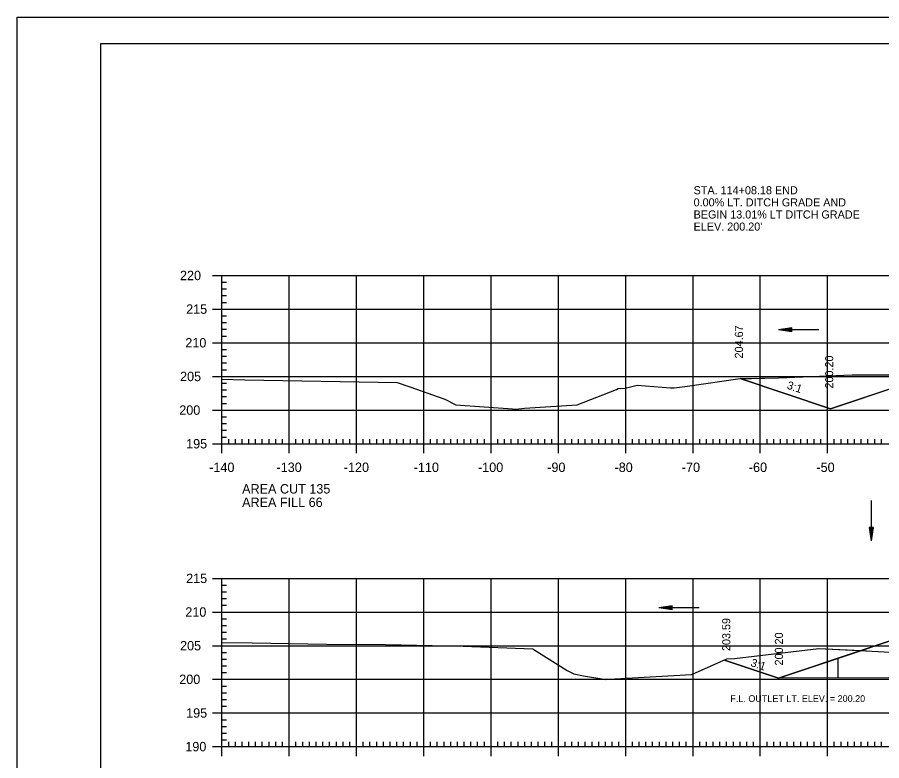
# Model space of a CAD drawing. Extents: x 1312042 to 1371461, y 379929 to 1834241.
# Drawn here: x 1371127.9 to 1371256.3, y 380031.8 to 380142.3 of the extents above; entities that cross this region are included whole.
import ezdxf

# ---------------------------------------------------------------- set-up
doc = ezdxf.new("R2010")
doc.units = 0
for name, color, linetype in [('R_Axis', 7, 'Continuous'), ('R_Axis Annot', 7, 'Continuous'), ('R_Border', 7, 'Continuous'), ('R_Drive', 7, 'Continuous'), ('R_Exist Surface', 7, 'Continuous'), ('R_Fin Surface', 7, 'Continuous'), ('R_Grid', 7, 'Continuous'), ('R_No Plot', 7, 'Continuous'), ('R_Water', 7, 'Continuous'), ('R_Water Annot', 7, 'Continuous'), ('R_Xsect Elev', 7, 'Continuous'), ('R_Xsect Slope', 7, 'Continuous')]:
    doc.layers.add(name, color=color, linetype=linetype)

msp = doc.modelspace()

# ---------------------------------------------------------------- linework, layer by layer
at = {"layer": 'R_Axis'}
for p, q in [((1371156.88, 380103.91), (1371159.68, 380103.91)), ((1371158.28, 380078.91), (1371158.28, 380103.91)), ((1371158.28, 380102.91), (1371158.98, 380102.91)), ((1371158.28, 380101.91), (1371158.98, 380101.91)), ((1371158.28, 380100.91), (1371158.98, 380100.91)), ((1371158.28, 380099.91), (1371158.98, 380099.91)), ((1371156.88, 380098.91), (1371159.68, 380098.91)), ((1371158.28, 380097.91), (1371158.98, 380097.91)), ((1371158.28, 380096.91), (1371158.98, 380096.91)), ((1371158.28, 380095.91), (1371158.98, 380095.91)), ((1371158.28, 380094.91), (1371158.98, 380094.91)), ((1371156.88, 380093.91), (1371159.68, 380093.91)), ((1371158.28, 380092.91), (1371158.98, 380092.91)), ((1371158.28, 380091.91), (1371158.98, 380091.91)), ((1371158.28, 380090.91), (1371158.98, 380090.91)), ((1371156.88, 380088.91), (1371159.68, 380088.91)), ((1371158.28, 380089.91), (1371158.98, 380089.91)), ((1371158.28, 380087.91), (1371158.98, 380087.91)), ((1371158.28, 380086.91), (1371158.98, 380086.91)), ((1371158.28, 380085.91), (1371158.98, 380085.91)), ((1371156.88, 380083.91), (1371159.68, 380083.91)), ((1371158.28, 380084.91), (1371158.98, 380084.91)), ((1371158.28, 380082.91), (1371158.98, 380082.91)), ((1371158.28, 380081.91), (1371158.98, 380081.91)), ((1371158.28, 380080.91), (1371158.98, 380080.91)), ((1371158.28, 380077.51), (1371158.28, 380080.31)), ((1371168.28, 380077.51), (1371168.28, 380080.31)), ((1371178.28, 380077.51), (1371178.28, 380080.31)), ((1371188.28, 380077.51), (1371188.28, 380080.31)), ((1371198.28, 380077.51), (1371198.28, 380080.31)), ((1371208.28, 380077.51), (1371208.28, 380080.31)), ((1371218.28, 380077.51), (1371218.28, 380080.31)), ((1371228.28, 380077.51), (1371228.28, 380080.31)), ((1371238.28, 380077.51), (1371238.28, 380080.31)), ((1371248.28, 380077.51), (1371248.28, 380080.31)), ((1371156.88, 380078.91), (1371159.68, 380078.91)), ((1371158.28, 380079.91), (1371158.98, 380079.91)), ((1371158.28, 380078.91), (1371438.28, 380078.91)), ((1371159.28, 380078.91), (1371159.28, 380079.61)), ((1371160.28, 380078.91), (1371160.28, 380079.61)), ((1371161.28, 380078.91), (1371161.28, 380079.61)), ((1371162.28, 380078.91), (1371162.28, 380079.61)), ((1371163.28, 380078.91), (1371163.28, 380079.61)), ((1371164.28, 380078.91), (1371164.28, 380079.61)), ((1371165.28, 380078.91), (1371165.28, 380079.61)), ((1371166.28, 380078.91), (1371166.28, 380079.61)), ((1371167.28, 380078.91), (1371167.28, 380079.61)), ((1371169.28, 380078.91), (1371169.28, 380079.61)), ((1371170.28, 380078.91), (1371170.28, 380079.61)), ((1371171.28, 380078.91), (1371171.28, 380079.61)), ((1371172.28, 380078.91), (1371172.28, 380079.61)), ((1371173.28, 380078.91), (1371173.28, 380079.61)), ((1371174.28, 380078.91), (1371174.28, 380079.61)), ((1371175.28, 380078.91), (1371175.28, 380079.61)), ((1371176.28, 380078.91), (1371176.28, 380079.61)), ((1371177.28, 380078.91), (1371177.28, 380079.61)), ((1371179.28, 380078.91), (1371179.28, 380079.61)), ((1371180.28, 380078.91), (1371180.28, 380079.61)), ((1371181.28, 380078.91), (1371181.28, 380079.61)), ((1371182.28, 380078.91), (1371182.28, 380079.61)), ((1371183.28, 380078.91), (1371183.28, 380079.61)), ((1371184.28, 380078.91), (1371184.28, 380079.61)), ((1371185.28, 380078.91), (1371185.28, 380079.61)), ((1371186.28, 380078.91), (1371186.28, 380079.61)), ((1371187.28, 380078.91), (1371187.28, 380079.61)), ((1371189.28, 380078.91), (1371189.28, 380079.61)), ((1371190.28, 380078.91), (1371190.28, 380079.61)), ((1371191.28, 380078.91), (1371191.28, 380079.61)), ((1371192.28, 380078.91), (1371192.28, 380079.61)), ((1371193.28, 380078.91), (1371193.28, 380079.61)), ((1371194.28, 380078.91), (1371194.28, 380079.61)), ((1371195.28, 380078.91), (1371195.28, 380079.61)), ((1371196.28, 380078.91), (1371196.28, 380079.61)), ((1371197.28, 380078.91), (1371197.28, 380079.61)), ((1371199.28, 380078.91), (1371199.28, 380079.61)), ((1371200.28, 380078.91), (1371200.28, 380079.61)), ((1371201.28, 380078.91), (1371201.28, 380079.61)), ((1371202.28, 380078.91), (1371202.28, 380079.61)), ((1371203.28, 380078.91), (1371203.28, 380079.61)), ((1371204.28, 380078.91), (1371204.28, 380079.61)), ((1371205.28, 380078.91), (1371205.28, 380079.61)), ((1371206.28, 380078.91), (1371206.28, 380079.61)), ((1371207.28, 380078.91), (1371207.28, 380079.61)), ((1371209.28, 380078.91), (1371209.28, 380079.61)), ((1371210.28, 380078.91), (1371210.28, 380079.61)), ((1371211.28, 380078.91), (1371211.28, 380079.61)), ((1371212.28, 380078.91), (1371212.28, 380079.61)), ((1371213.28, 380078.91), (1371213.28, 380079.61)), ((1371214.28, 380078.91), (1371214.28, 380079.61)), ((1371215.28, 380078.91), (1371215.28, 380079.61)), ((1371216.28, 380078.91), (1371216.28, 380079.61)), ((1371217.28, 380078.91), (1371217.28, 380079.61)), ((1371219.28, 380078.91), (1371219.28, 380079.61)), ((1371220.28, 380078.91), (1371220.28, 380079.61)), ((1371221.28, 380078.91), (1371221.28, 380079.61)), ((1371222.28, 380078.91), (1371222.28, 380079.61)), ((1371223.28, 380078.91), (1371223.28, 380079.61)), ((1371224.28, 380078.91), (1371224.28, 380079.61)), ((1371225.28, 380078.91), (1371225.28, 380079.61)), ((1371226.28, 380078.91), (1371226.28, 380079.61)), ((1371227.28, 380078.91), (1371227.28, 380079.61)), ((1371229.28, 380078.91), (1371229.28, 380079.61)), ((1371230.28, 380078.91), (1371230.28, 380079.61)), ((1371231.28, 380078.91), (1371231.28, 380079.61)), ((1371232.28, 380078.91), (1371232.28, 380079.61)), ((1371233.28, 380078.91), (1371233.28, 380079.61)), ((1371234.28, 380078.91), (1371234.28, 380079.61)), ((1371235.28, 380078.91), (1371235.28, 380079.61)), ((1371236.28, 380078.91), (1371236.28, 380079.61)), ((1371237.28, 380078.91), (1371237.28, 380079.61)), ((1371239.28, 380078.91), (1371239.28, 380079.61)), ((1371240.28, 380078.91), (1371240.28, 380079.61)), ((1371241.28, 380078.91), (1371241.28, 380079.61)), ((1371242.28, 380078.91), (1371242.28, 380079.61)), ((1371243.28, 380078.91), (1371243.28, 380079.61)), ((1371244.28, 380078.91), (1371244.28, 380079.61)), ((1371245.28, 380078.91), (1371245.28, 380079.61)), ((1371246.28, 380078.91), (1371246.28, 380079.61)), ((1371247.28, 380078.91), (1371247.28, 380079.61)), ((1371249.28, 380078.91), (1371249.28, 380079.61)), ((1371250.28, 380078.91), (1371250.28, 380079.61)), ((1371251.28, 380078.91), (1371251.28, 380079.61)), ((1371252.28, 380078.91), (1371252.28, 380079.61)), ((1371253.28, 380078.91), (1371253.28, 380079.61)), ((1371254.28, 380078.91), (1371254.28, 380079.61)), ((1371255.28, 380078.91), (1371255.28, 380079.61)), ((1371256.28, 380078.91), (1371256.28, 380079.61)), ((1371156.88, 380058.91), (1371159.68, 380058.91)), ((1371158.28, 380033.91), (1371158.28, 380058.91)), ((1371158.28, 380057.91), (1371158.98, 380057.91)), ((1371158.28, 380056.91), (1371158.98, 380056.91)), ((1371158.28, 380055.91), (1371158.98, 380055.91)), ((1371158.28, 380054.91), (1371158.98, 380054.91)), ((1371156.88, 380053.91), (1371159.68, 380053.91)), ((1371158.28, 380052.91), (1371158.98, 380052.91)), ((1371158.28, 380051.91), (1371158.98, 380051.91)), ((1371158.28, 380050.91), (1371158.98, 380050.91)), ((1371158.28, 380049.91), (1371158.98, 380049.91)), ((1371156.88, 380048.91), (1371159.68, 380048.91)), ((1371158.28, 380047.91), (1371158.98, 380047.91)), ((1371158.28, 380046.91), (1371158.98, 380046.91)), ((1371158.28, 380045.91), (1371158.98, 380045.91)), ((1371158.28, 380044.91), (1371158.98, 380044.91)), ((1371156.88, 380043.91), (1371159.68, 380043.91)), ((1371158.28, 380042.91), (1371158.98, 380042.91)), ((1371158.28, 380041.91), (1371158.98, 380041.91)), ((1371158.28, 380040.91), (1371158.98, 380040.91)), ((1371156.88, 380038.91), (1371159.68, 380038.91)), ((1371158.28, 380039.91), (1371158.98, 380039.91)), ((1371158.28, 380037.91), (1371158.98, 380037.91)), ((1371158.28, 380036.91), (1371158.98, 380036.91)), ((1371158.28, 380035.91), (1371158.98, 380035.91)), ((1371158.28, 380032.51), (1371158.28, 380035.31)), ((1371168.28, 380032.51), (1371168.28, 380035.31)), ((1371178.28, 380032.51), (1371178.28, 380035.31)), ((1371188.28, 380032.51), (1371188.28, 380035.31)), ((1371198.28, 380032.51), (1371198.28, 380035.31)), ((1371208.28, 380032.51), (1371208.28, 380035.31)), ((1371218.28, 380032.51), (1371218.28, 380035.31)), ((1371228.28, 380032.51), (1371228.28, 380035.31)), ((1371238.28, 380032.51), (1371238.28, 380035.31)), ((1371248.28, 380032.51), (1371248.28, 380035.31)), ((1371156.88, 380033.91), (1371159.68, 380033.91)), ((1371158.28, 380034.91), (1371158.98, 380034.91)), ((1371158.28, 380033.91), (1371438.28, 380033.91)), ((1371159.28, 380033.91), (1371159.28, 380034.61)), ((1371160.28, 380033.91), (1371160.28, 380034.61)), ((1371161.28, 380033.91), (1371161.28, 380034.61)), ((1371162.28, 380033.91), (1371162.28, 380034.61)), ((1371163.28, 380033.91), (1371163.28, 380034.61)), ((1371164.28, 380033.91), (1371164.28, 380034.61)), ((1371165.28, 380033.91), (1371165.28, 380034.61)), ((1371166.28, 380033.91), (1371166.28, 380034.61)), ((1371167.28, 380033.91), (1371167.28, 380034.61)), ((1371169.28, 380033.91), (1371169.28, 380034.61)), ((1371170.28, 380033.91), (1371170.28, 380034.61)), ((1371171.28, 380033.91), (1371171.28, 380034.61)), ((1371172.28, 380033.91), (1371172.28, 380034.61)), ((1371173.28, 380033.91), (1371173.28, 380034.61)), ((1371174.28, 380033.91), (1371174.28, 380034.61)), ((1371175.28, 380033.91), (1371175.28, 380034.61)), ((1371176.28, 380033.91), (1371176.28, 380034.61)), ((1371177.28, 380033.91), (1371177.28, 380034.61)), ((1371179.28, 380033.91), (1371179.28, 380034.61)), ((1371180.28, 380033.91), (1371180.28, 380034.61)), ((1371181.28, 380033.91), (1371181.28, 380034.61)), ((1371182.28, 380033.91), (1371182.28, 380034.61)), ((1371183.28, 380033.91), (1371183.28, 380034.61)), ((1371184.28, 380033.91), (1371184.28, 380034.61)), ((1371185.28, 380033.91), (1371185.28, 380034.61)), ((1371186.28, 380033.91), (1371186.28, 380034.61)), ((1371187.28, 380033.91), (1371187.28, 380034.61)), ((1371189.28, 380033.91), (1371189.28, 380034.61)), ((1371190.28, 380033.91), (1371190.28, 380034.61)), ((1371191.28, 380033.91), (1371191.28, 380034.61)), ((1371192.28, 380033.91), (1371192.28, 380034.61)), ((1371193.28, 380033.91), (1371193.28, 380034.61)), ((1371194.28, 380033.91), (1371194.28, 380034.61)), ((1371195.28, 380033.91), (1371195.28, 380034.61)), ((1371196.28, 380033.91), (1371196.28, 380034.61)), ((1371197.28, 380033.91), (1371197.28, 380034.61)), ((1371199.28, 380033.91), (1371199.28, 380034.61)), ((1371200.28, 380033.91), (1371200.28, 380034.61)), ((1371201.28, 380033.91), (1371201.28, 380034.61)), ((1371202.28, 380033.91), (1371202.28, 380034.61)), ((1371203.28, 380033.91), (1371203.28, 380034.61)), ((1371204.28, 380033.91), (1371204.28, 380034.61)), ((1371205.28, 380033.91), (1371205.28, 380034.61)), ((1371206.28, 380033.91), (1371206.28, 380034.61)), ((1371207.28, 380033.91), (1371207.28, 380034.61)), ((1371209.28, 380033.91), (1371209.28, 380034.61)), ((1371210.28, 380033.91), (1371210.28, 380034.61)), ((1371211.28, 380033.91), (1371211.28, 380034.61)), ((1371212.28, 380033.91), (1371212.28, 380034.61)), ((1371213.28, 380033.91), (1371213.28, 380034.61)), ((1371214.28, 380033.91), (1371214.28, 380034.61)), ((1371215.28, 380033.91), (1371215.28, 380034.61)), ((1371216.28, 380033.91), (1371216.28, 380034.61)), ((1371217.28, 380033.91), (1371217.28, 380034.61)), ((1371219.28, 380033.91), (1371219.28, 380034.61)), ((1371220.28, 380033.91), (1371220.28, 380034.61)), ((1371221.28, 380033.91), (1371221.28, 380034.61)), ((1371222.28, 380033.91), (1371222.28, 380034.61)), ((1371223.28, 380033.91), (1371223.28, 380034.61)), ((1371224.28, 380033.91), (1371224.28, 380034.61)), ((1371225.28, 380033.91), (1371225.28, 380034.61)), ((1371226.28, 380033.91), (1371226.28, 380034.61)), ((1371227.28, 380033.91), (1371227.28, 380034.61)), ((1371229.28, 380033.91), (1371229.28, 380034.61)), ((1371230.28, 380033.91), (1371230.28, 380034.61)), ((1371231.28, 380033.91), (1371231.28, 380034.61)), ((1371232.28, 380033.91), (1371232.28, 380034.61)), ((1371233.28, 380033.91), (1371233.28, 380034.61)), ((1371234.28, 380033.91), (1371234.28, 380034.61)), ((1371235.28, 380033.91), (1371235.28, 380034.61)), ((1371236.28, 380033.91), (1371236.28, 380034.61)), ((1371237.28, 380033.91), (1371237.28, 380034.61)), ((1371239.28, 380033.91), (1371239.28, 380034.61)), ((1371240.28, 380033.91), (1371240.28, 380034.61)), ((1371241.28, 380033.91), (1371241.28, 380034.61)), ((1371242.28, 380033.91), (1371242.28, 380034.61)), ((1371243.28, 380033.91), (1371243.28, 380034.61)), ((1371244.28, 380033.91), (1371244.28, 380034.61)), ((1371245.28, 380033.91), (1371245.28, 380034.61)), ((1371246.28, 380033.91), (1371246.28, 380034.61)), ((1371247.28, 380033.91), (1371247.28, 380034.61)), ((1371249.28, 380033.91), (1371249.28, 380034.61)), ((1371250.28, 380033.91), (1371250.28, 380034.61)), ((1371251.28, 380033.91), (1371251.28, 380034.61)), ((1371252.28, 380033.91), (1371252.28, 380034.61)), ((1371253.28, 380033.91), (1371253.28, 380034.61)), ((1371254.28, 380033.91), (1371254.28, 380034.61)), ((1371255.28, 380033.91), (1371255.28, 380034.61)), ((1371256.28, 380033.91), (1371256.28, 380034.61))]:
    msp.add_line(p, q, dxfattribs=at)
at = {"layer": 'R_Border'}
for p, q in [((1371140.28, 380138.37), (1371456.46, 380138.37)), ((1371140.28, 379932.91), (1371140.28, 380138.37))]:
    msp.add_line(p, q, dxfattribs=at)
at = {"layer": 'R_Exist Surface'}
for points in [[(1371158.28, 380088.48), (1371161.68, 380088.39), (1371184.33, 380088.02), (1371186.22, 380087.35), (1371191.42, 380085.52), (1371193.05, 380084.69), (1371201.47, 380084.1), (1371201.98, 380084.07), (1371203.26, 380084.19), (1371211.06, 380084.71), (1371216.89, 380086.99), (1371217.15, 380087.13), (1371218.21, 380087.17), (1371219.99, 380087.63), (1371224.93, 380087.23), (1371225.5, 380087.21), (1371227.45, 380087.44), (1371234.95, 380088.57), (1371240.97, 380088.71), (1371251.91, 380089.15), (1371257.83, 380089.15)], [(1371158.28, 380049.4), (1371162.77, 380049.31), (1371173.82, 380049.11), (1371182.58, 380049.06), (1371194.12, 380048.86), (1371204.47, 380048.43), (1371204.76, 380048.24), (1371209.58, 380045.22), (1371210.57, 380044.75), (1371212.03, 380044.42), (1371215.32, 380043.87), (1371215.81, 380043.93), (1371216.67, 380044), (1371228.07, 380044.63), (1371228.65, 380044.87), (1371233.33, 380046.94), (1371234.47, 380047.02), (1371246.99, 380048.49), (1371254.91, 380048.1), (1371267.41, 380047.41)]]:
    msp.add_lwpolyline(points, dxfattribs=at)
at = {"layer": 'R_Fin Surface'}
for points in [[(1371235.3, 380088.58), (1371248.72, 380084.11), (1371269.28, 380090.96), (1371280.36, 380093.73), (1371283.28, 380094.46), (1371287.28, 380094.62), (1371298.28, 380094.84), (1371309.28, 380094.62), (1371313.28, 380094.46), (1371316.19, 380093.73), (1371327.28, 380090.96), (1371347.24, 380084.31), (1371355.55, 380089.71)], [(1371232.95, 380046.77), (1371240.98, 380044.09), (1371268.27, 380053.19), (1371269.27, 380053.19), (1371283.28, 380054.47), (1371287.28, 380054.63), (1371298.28, 380054.85), (1371309.28, 380054.63), (1371313.28, 380054.47), (1371327.27, 380053.31), (1371328.27, 380053.31), (1371355.24, 380044.33), (1371357.28, 380045.35)]]:
    msp.add_lwpolyline(points, dxfattribs=at)
at = {"layer": 'R_Grid'}
for p, q in [((1371158.28, 380103.91), (1371438.28, 380103.91)), ((1371158.28, 380078.91), (1371158.28, 380103.91)), ((1371168.28, 380078.91), (1371168.28, 380103.91)), ((1371178.28, 380078.91), (1371178.28, 380103.91)), ((1371188.28, 380078.91), (1371188.28, 380103.91)), ((1371198.28, 380078.91), (1371198.28, 380103.91)), ((1371208.28, 380078.91), (1371208.28, 380103.91)), ((1371218.28, 380078.91), (1371218.28, 380103.91)), ((1371228.28, 380078.91), (1371228.28, 380103.91)), ((1371238.28, 380078.91), (1371238.28, 380103.91)), ((1371248.28, 380078.91), (1371248.28, 380103.91)), ((1371158.28, 380098.91), (1371438.28, 380098.91)), ((1371158.28, 380093.91), (1371438.28, 380093.91)), ((1371158.28, 380088.91), (1371438.28, 380088.91)), ((1371158.28, 380083.91), (1371438.28, 380083.91)), ((1371158.28, 380078.91), (1371438.28, 380078.91)), ((1371158.28, 380058.91), (1371438.28, 380058.91)), ((1371158.28, 380033.91), (1371158.28, 380058.91)), ((1371168.28, 380033.91), (1371168.28, 380058.91)), ((1371178.28, 380033.91), (1371178.28, 380058.91)), ((1371188.28, 380033.91), (1371188.28, 380058.91)), ((1371198.28, 380033.91), (1371198.28, 380058.91)), ((1371208.28, 380033.91), (1371208.28, 380058.91)), ((1371218.28, 380033.91), (1371218.28, 380058.91)), ((1371228.28, 380033.91), (1371228.28, 380058.91)), ((1371238.28, 380033.91), (1371238.28, 380058.91)), ((1371248.28, 380033.91), (1371248.28, 380058.91)), ((1371158.28, 380053.91), (1371438.28, 380053.91)), ((1371158.28, 380048.91), (1371438.28, 380048.91)), ((1371158.28, 380043.91), (1371438.28, 380043.91)), ((1371158.28, 380038.91), (1371438.28, 380038.91)), ((1371158.28, 380033.91), (1371438.28, 380033.91))]:
    msp.add_line(p, q, dxfattribs=at)
at = {"layer": 'R_No Plot'}
msp.add_line((1371127.88, 380142.26), (1371461.21, 380142.26), dxfattribs=at)
for points in [[(1371127.87, 380142.26), (1371461.21, 380142.26), (1371461.21, 379928.93), (1371127.87, 379928.93)], [(1371374.2, 380138.37), (1371374.2, 380128.49), (1371409.93, 380128.49), (1371409.93, 380125.57), (1371433.13, 380125.57), (1371433.13, 380101.24), (1371456.46, 380101.24), (1371456.46, 379932.91), (1371140.28, 379932.91), (1371140.28, 380138.37)], [(1371235.3, 380088.58), (1371240.97, 380088.71), (1371251.91, 380089.15), (1371257.83, 380089.15), (1371263.55, 380089.06), (1371248.72, 380084.11)], [(1371232.95, 380046.77), (1371233.33, 380046.94), (1371234.47, 380047.02), (1371246.99, 380048.49), (1371253.25, 380048.18), (1371240.98, 380044.09)]]:
    msp.add_lwpolyline(points, close=True, dxfattribs=at)
msp.add_lwpolyline([(1371268.27, 380053.19), (1371253.25, 380048.18), (1371254.91, 380048.1), (1371267.41, 380047.41)], dxfattribs=at)
at = {"layer": 'R_Water'}
for p, q in [((1371240.98, 380044.09), (1371232.95, 380046.77)), ((1371249.79, 380047.03), (1371249.79, 380044.11)), ((1371355.24, 380044.33), (1371240.98, 380044.09))]:
    msp.add_line(p, q, dxfattribs=at)
at = {"layer": 'R_Water Annot'}
for p, q in [((1371242.99, 380096.12), (1371240.99, 380095.82)), ((1371246.99, 380095.82), (1371240.99, 380095.82)), ((1371242.99, 380095.52), (1371240.99, 380095.82)), ((1371242.99, 380096.07), (1371241.32, 380095.82)), ((1371242.99, 380095.57), (1371241.32, 380095.82)), ((1371242.99, 380096.02), (1371241.66, 380095.82)), ((1371242.99, 380095.62), (1371241.66, 380095.82)), ((1371242.99, 380095.97), (1371242, 380095.82)), ((1371242.99, 380095.67), (1371242, 380095.82)), ((1371242.99, 380095.92), (1371242.34, 380095.82)), ((1371242.99, 380095.72), (1371242.34, 380095.82)), ((1371242.99, 380095.87), (1371242.67, 380095.82)), ((1371242.99, 380095.77), (1371242.67, 380095.82)), ((1371242.99, 380095.52), (1371242.99, 380096.12)), ((1371254.76, 380070.47), (1371254.76, 380064.47)), ((1371254.46, 380066.47), (1371254.76, 380064.47)), ((1371255.06, 380066.47), (1371254.46, 380066.47)), ((1371254.51, 380066.47), (1371254.76, 380064.81)), ((1371254.56, 380066.47), (1371254.76, 380065.15)), ((1371254.61, 380066.47), (1371254.76, 380065.48)), ((1371254.66, 380066.47), (1371254.76, 380065.82)), ((1371254.72, 380066.47), (1371254.76, 380066.16)), ((1371255.06, 380066.47), (1371254.76, 380064.47)), ((1371254.86, 380066.47), (1371254.76, 380065.82)), ((1371254.96, 380066.47), (1371254.76, 380065.15)), ((1371255.01, 380066.47), (1371254.76, 380064.81)), ((1371254.91, 380066.47), (1371254.76, 380065.48)), ((1371254.81, 380066.47), (1371254.76, 380066.16)), ((1371225.2, 380054.85), (1371223.2, 380054.55)), ((1371229.2, 380054.55), (1371223.2, 380054.55)), ((1371225.2, 380054.25), (1371223.2, 380054.55)), ((1371225.2, 380054.8), (1371223.54, 380054.55)), ((1371225.2, 380054.3), (1371223.54, 380054.55)), ((1371225.2, 380054.75), (1371223.88, 380054.55)), ((1371225.2, 380054.35), (1371223.88, 380054.55)), ((1371225.2, 380054.7), (1371224.21, 380054.55)), ((1371225.2, 380054.4), (1371224.21, 380054.55)), ((1371225.2, 380054.65), (1371224.55, 380054.55)), ((1371225.2, 380054.45), (1371224.55, 380054.55)), ((1371225.2, 380054.6), (1371224.89, 380054.55)), ((1371225.2, 380054.5), (1371224.89, 380054.55)), ((1371225.2, 380054.25), (1371225.2, 380054.85))]:
    msp.add_line(p, q, dxfattribs=at)

# ---------------------------------------------------------------- texts
at = {"layer": 'R_Axis Annot'}
for s, height, p in [('220', 1.4, (1371152.05, 380103.21)), ('215', 1.4, (1371152.96, 380098.21)), ('210', 1.4, (1371152.84, 380093.21)), ('205', 1.4, (1371152.06, 380088.21)), ('200', 1.4, (1371151.94, 380083.21)), ('195', 1.4, (1371152.96, 380078.21)), ('-140', 1.4, (1371156.39, 380074.71)), ('-130', 1.4, (1371166.39, 380074.71)), ('-120', 1.4, (1371176.39, 380074.71)), ('-110', 1.4, (1371186.78, 380074.71)), ('-100', 1.4, (1371196.33, 380074.71)), ('-90', 1.4, (1371206.62, 380074.71)), ('-80', 1.4, (1371216.62, 380074.71)), ('-70', 1.4, (1371226.62, 380074.71)), ('-60', 1.4, (1371236.58, 380074.71)), ('-50', 1.4, (1371246.62, 380074.71)), ('AREA CUT 135', 1.4, (1371161.28, 380071.51)), ('AREA FILL 66', 1.4, (1371161.28, 380069.51)), ('215', 1.4, (1371152.96, 380058.21)), ('210', 1.4, (1371152.84, 380053.21)), ('205', 1.4, (1371152.06, 380048.21)), ('200', 1.4, (1371151.94, 380043.21)), ('F.L. OUTLET LT. ELEV. = 200.20', 1, (1371233.83, 380040.55)), ('195', 1.4, (1371152.96, 380038.21)), ('190', 1.4, (1371152.84, 380033.21))]:
    msp.add_text(s, height=height, dxfattribs=at).set_placement(p)
at = {"layer": 'R_Drive'}
for s, p in [('STA. 114+08.18 END', (1371228.37, 380115.97)), ('0.00% LT. DITCH GRADE AND', (1371228.37, 380114.17)), ('BEGIN 13.01% LT DITCH GRADE', (1371228.37, 380112.37)), ("ELEV. 200.20'", (1371228.37, 380110.57))]:
    msp.add_text(s, height=1.2, dxfattribs=at).set_placement(p)
at = {"layer": 'R_Xsect Elev'}
for s, p in [('204.67', (1371235.7, 380091.58)), ('200.20', (1371249.12, 380087.11)), ('203.59', (1371233.82, 380048.11)), ('200.20', (1371241.64, 380045.97))]:
    msp.add_text(s, height=1.2, rotation=90, dxfattribs=at).set_placement(p)
at = {"layer": 'R_Xsect Slope'}
for p in [(1371242.14, 380087.12), (1371236.75, 380045.9)]:
    msp.add_text('3:1', height=1.2, rotation=341.5651, dxfattribs=at).set_placement(p)

doc.saveas('drawing.dxf')
